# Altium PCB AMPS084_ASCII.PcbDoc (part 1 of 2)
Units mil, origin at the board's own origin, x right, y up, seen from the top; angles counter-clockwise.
Board outline 7000 x 5000 mil, 4 copper layers (Top Layer, Int 2 V-, Int 3 V+, Bottom Layer), stack 61.634 mil thick; 175 components, 69 nets, 389 pads, 136 vias.
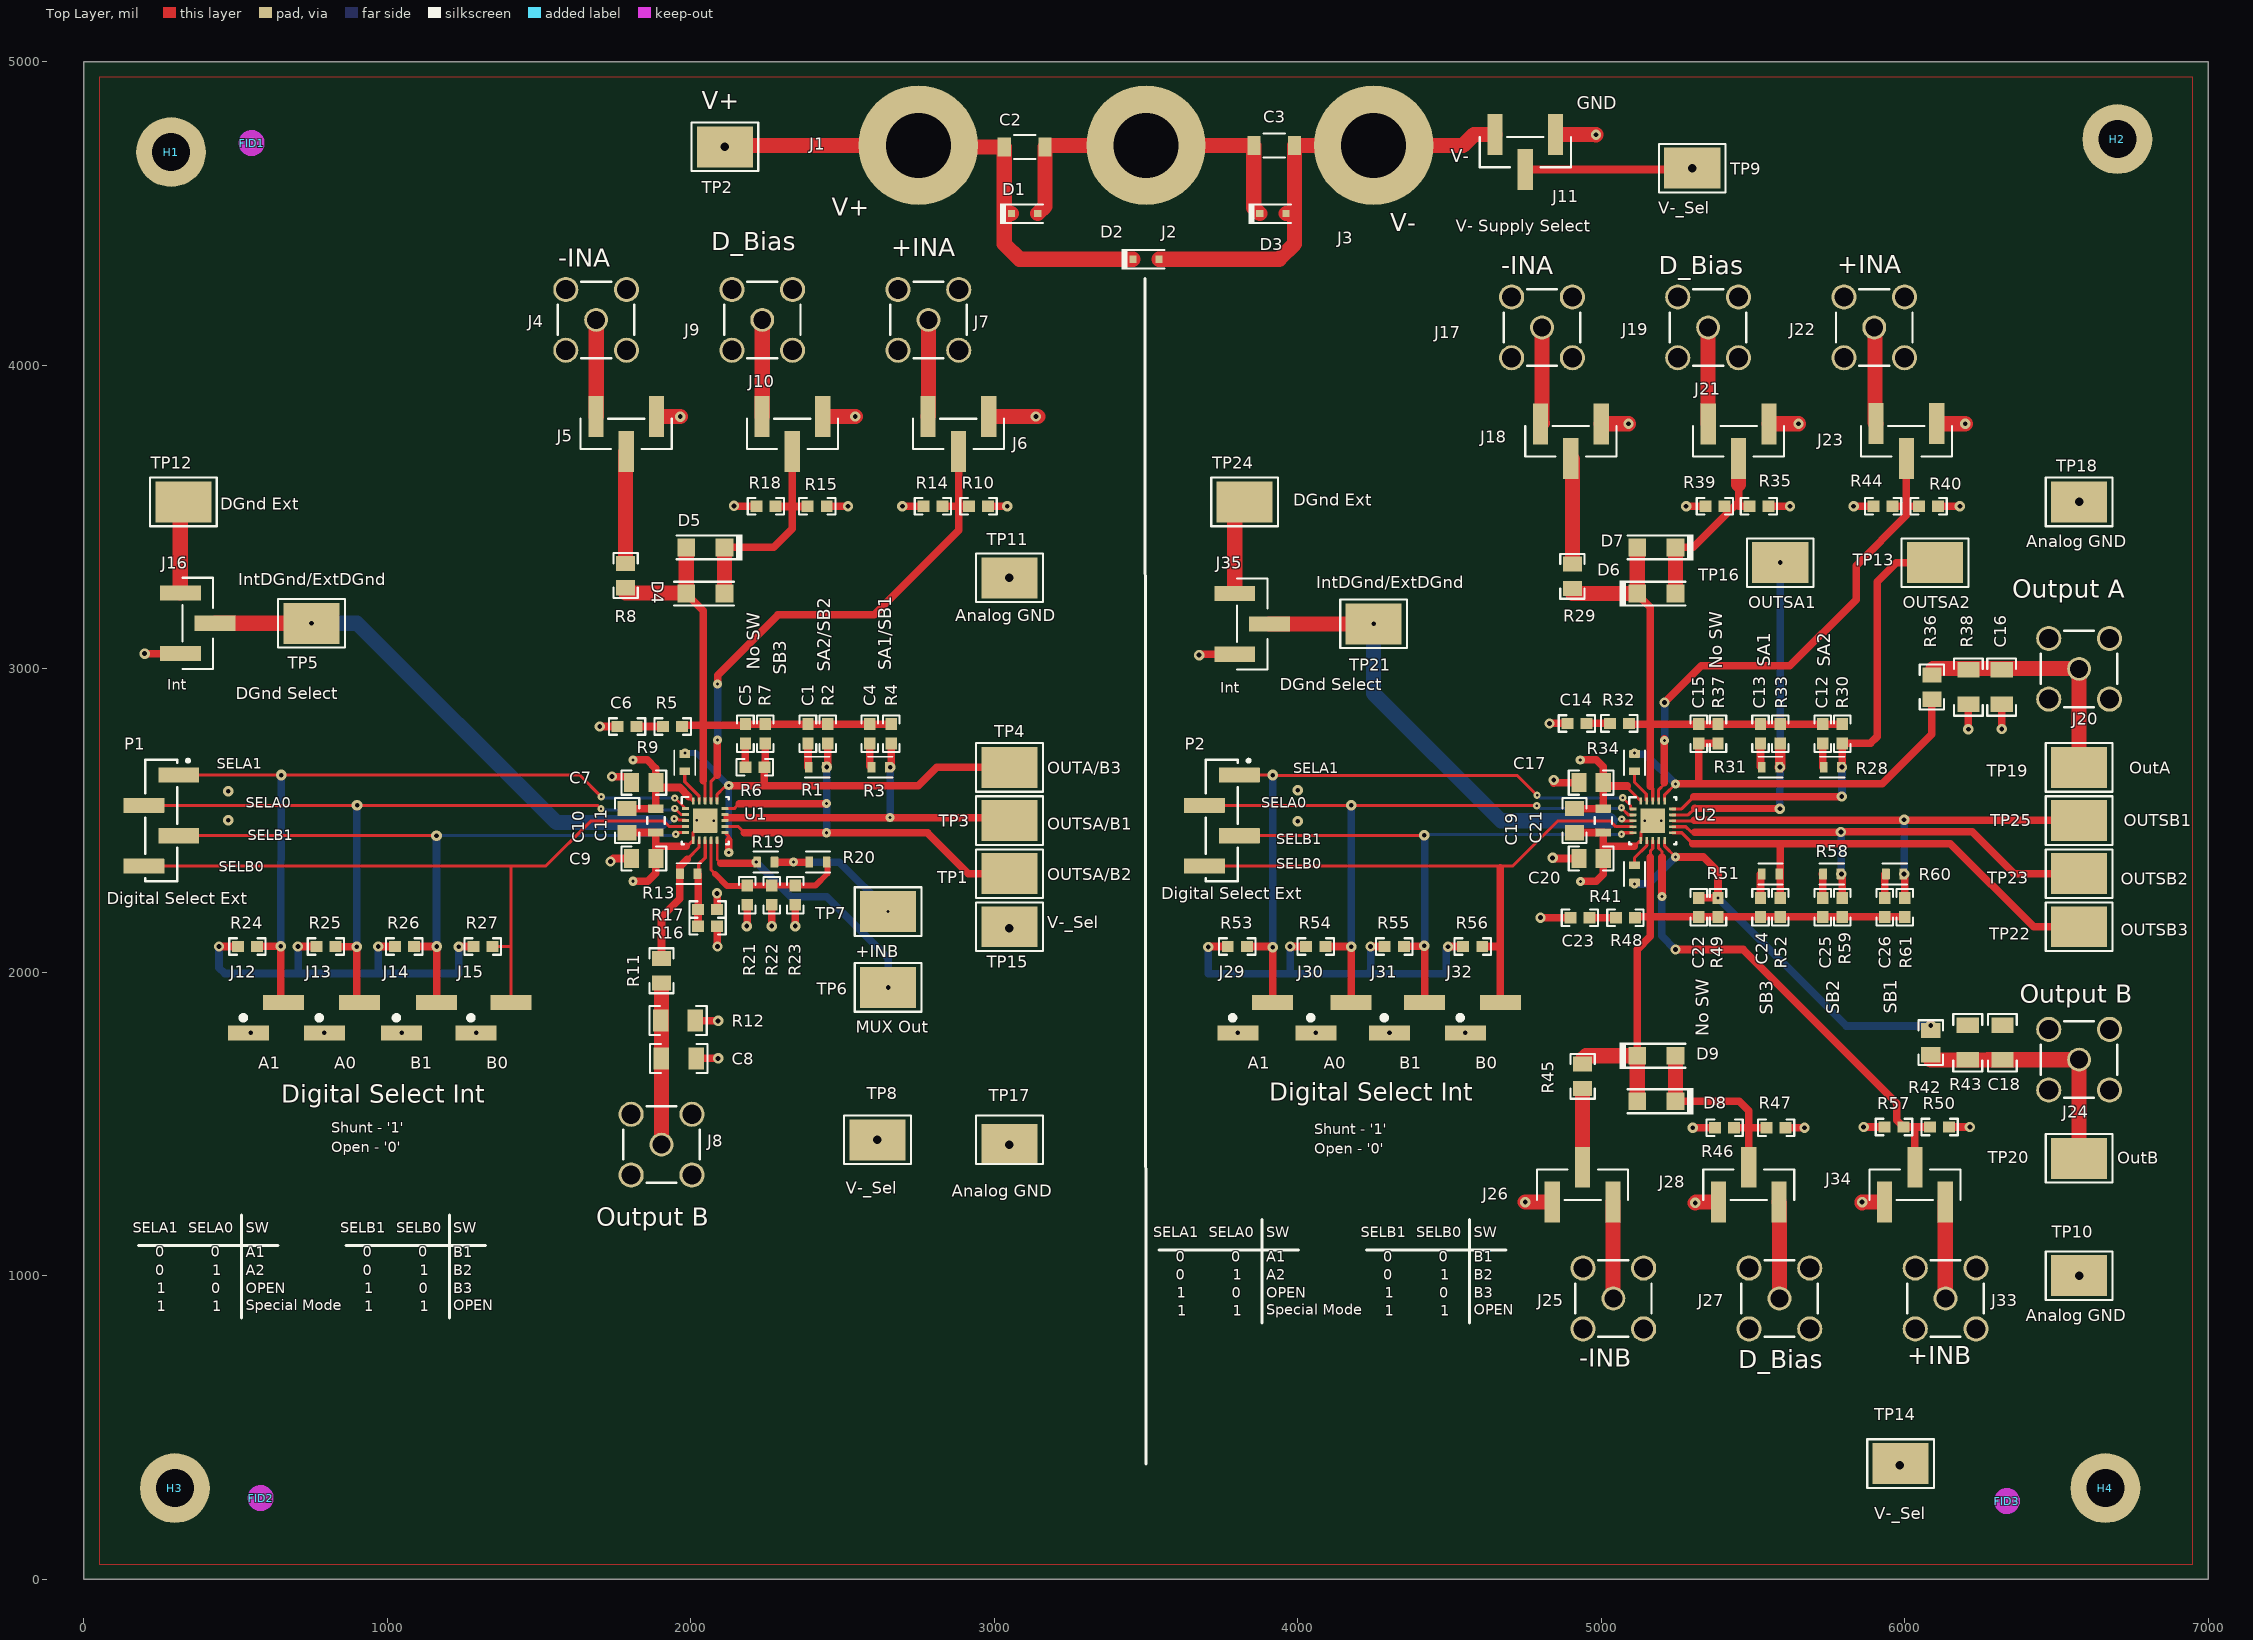
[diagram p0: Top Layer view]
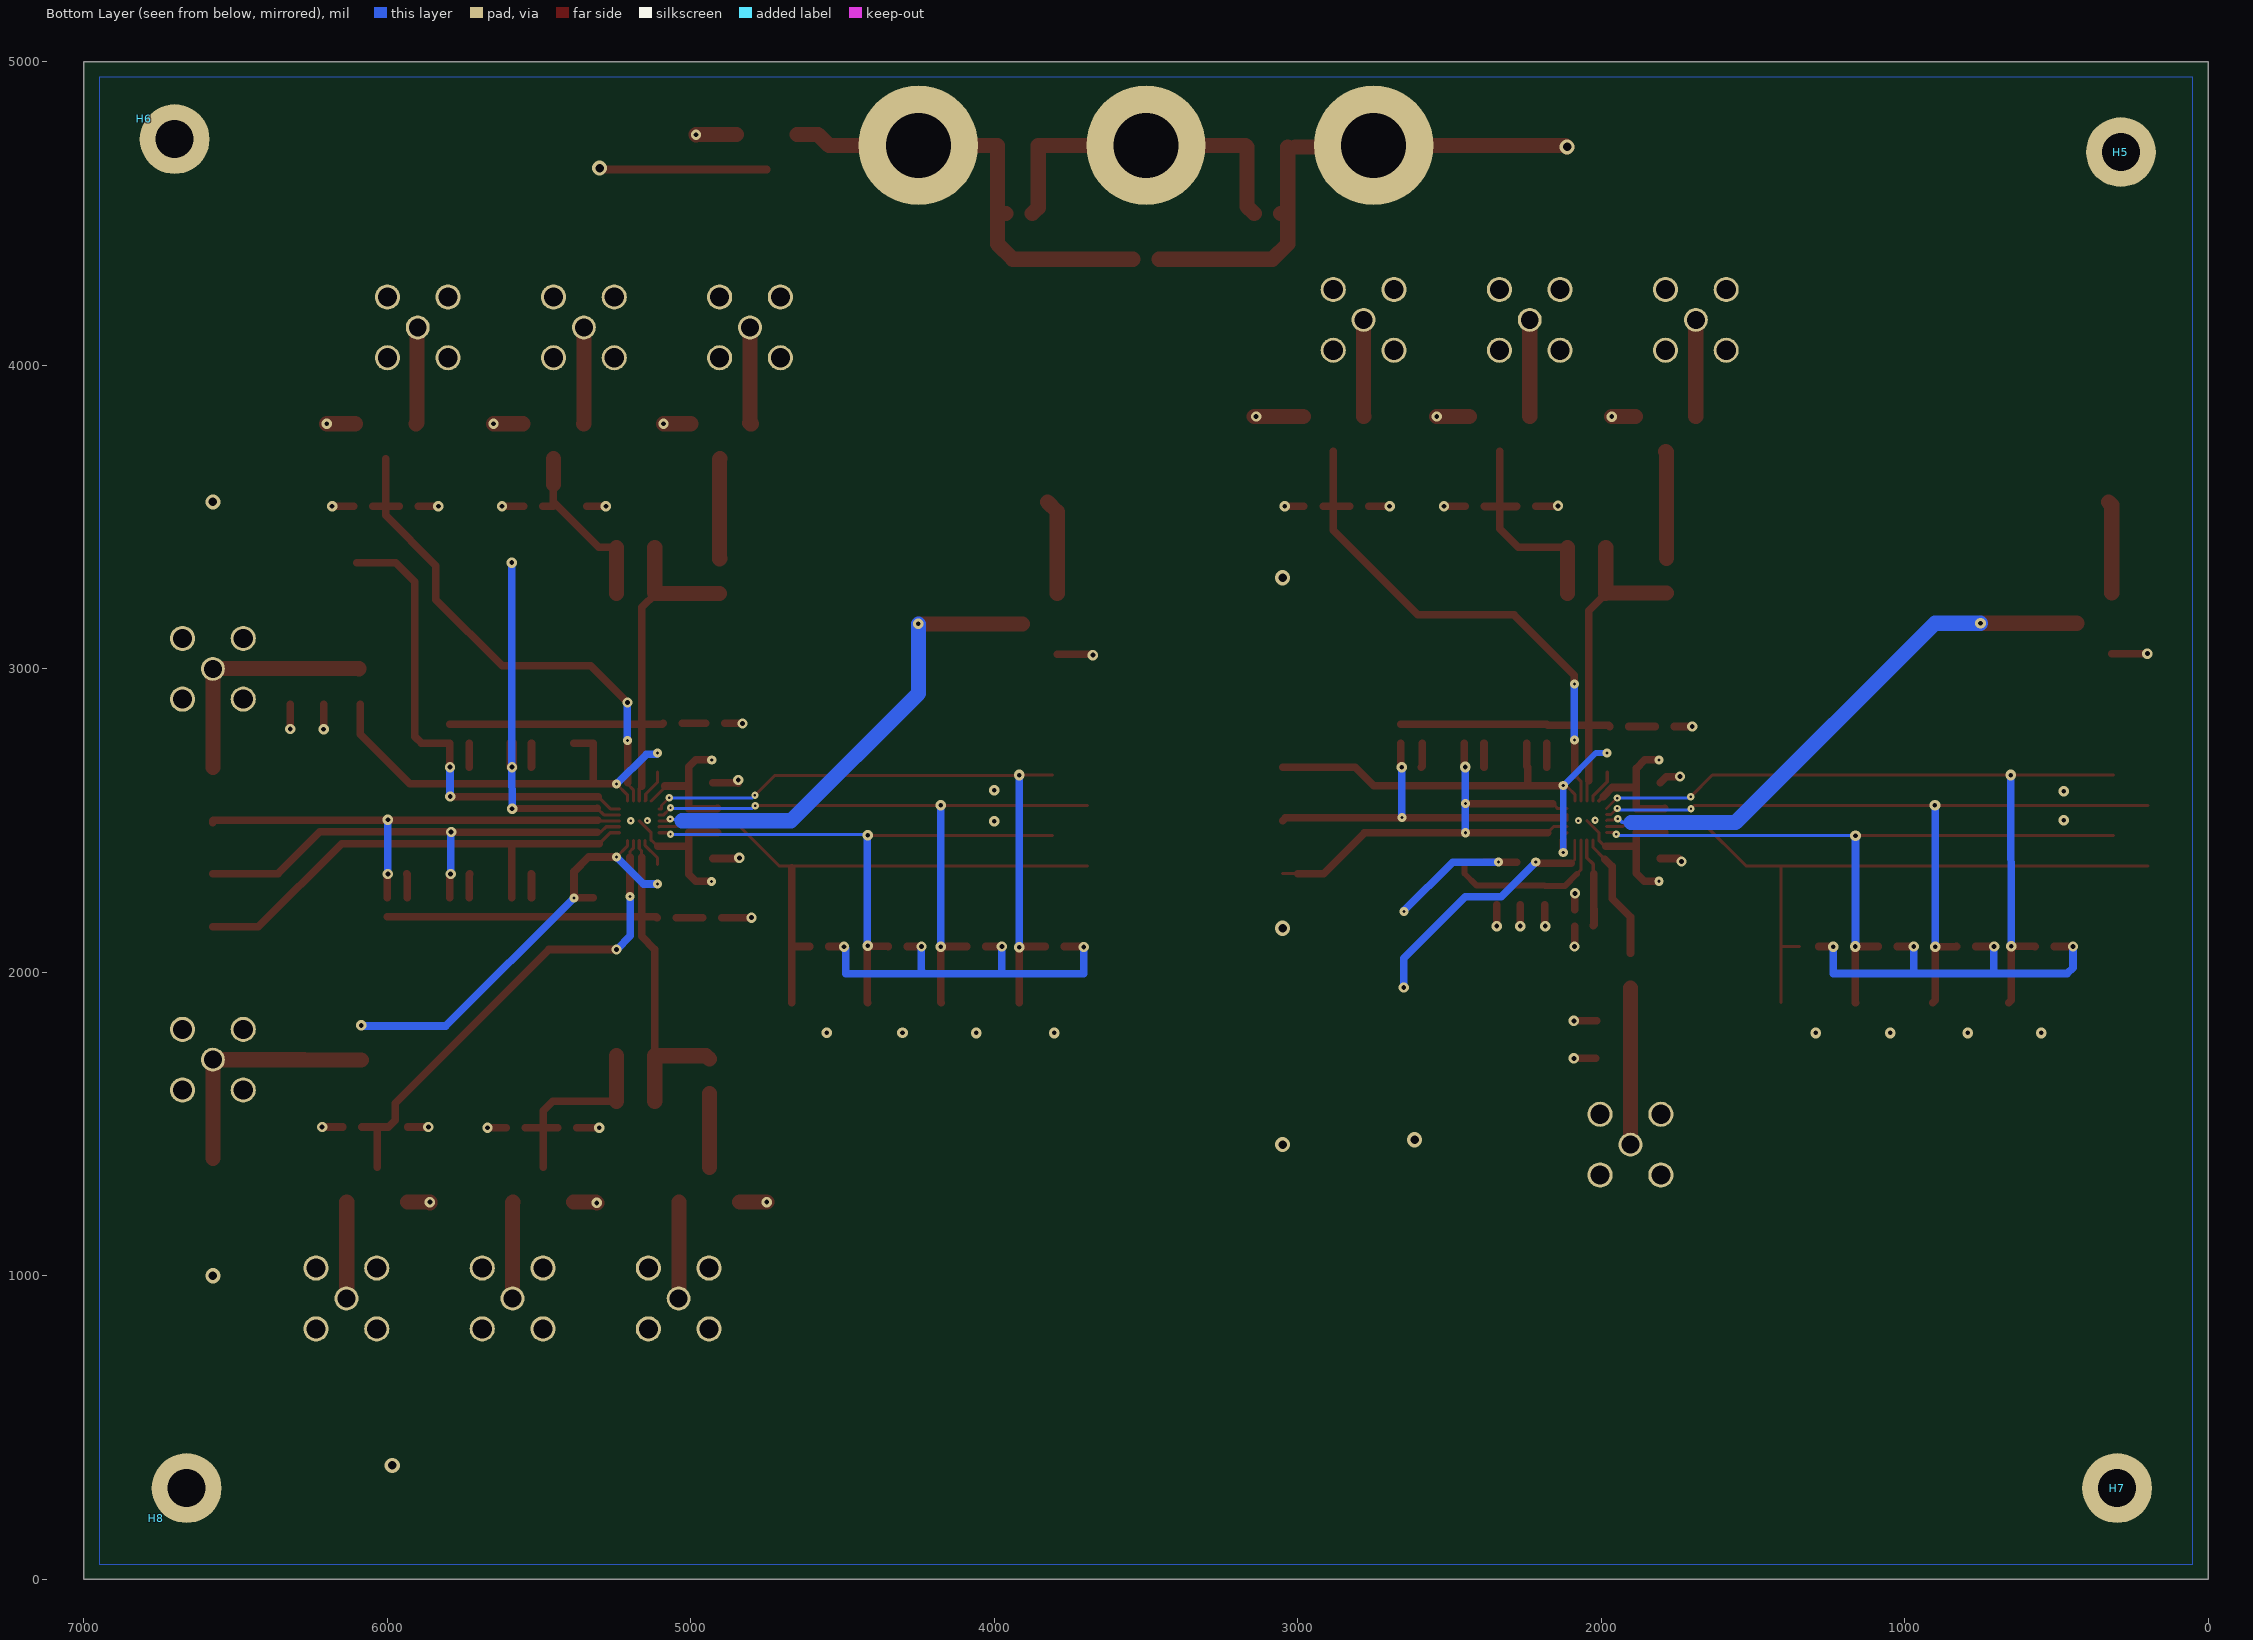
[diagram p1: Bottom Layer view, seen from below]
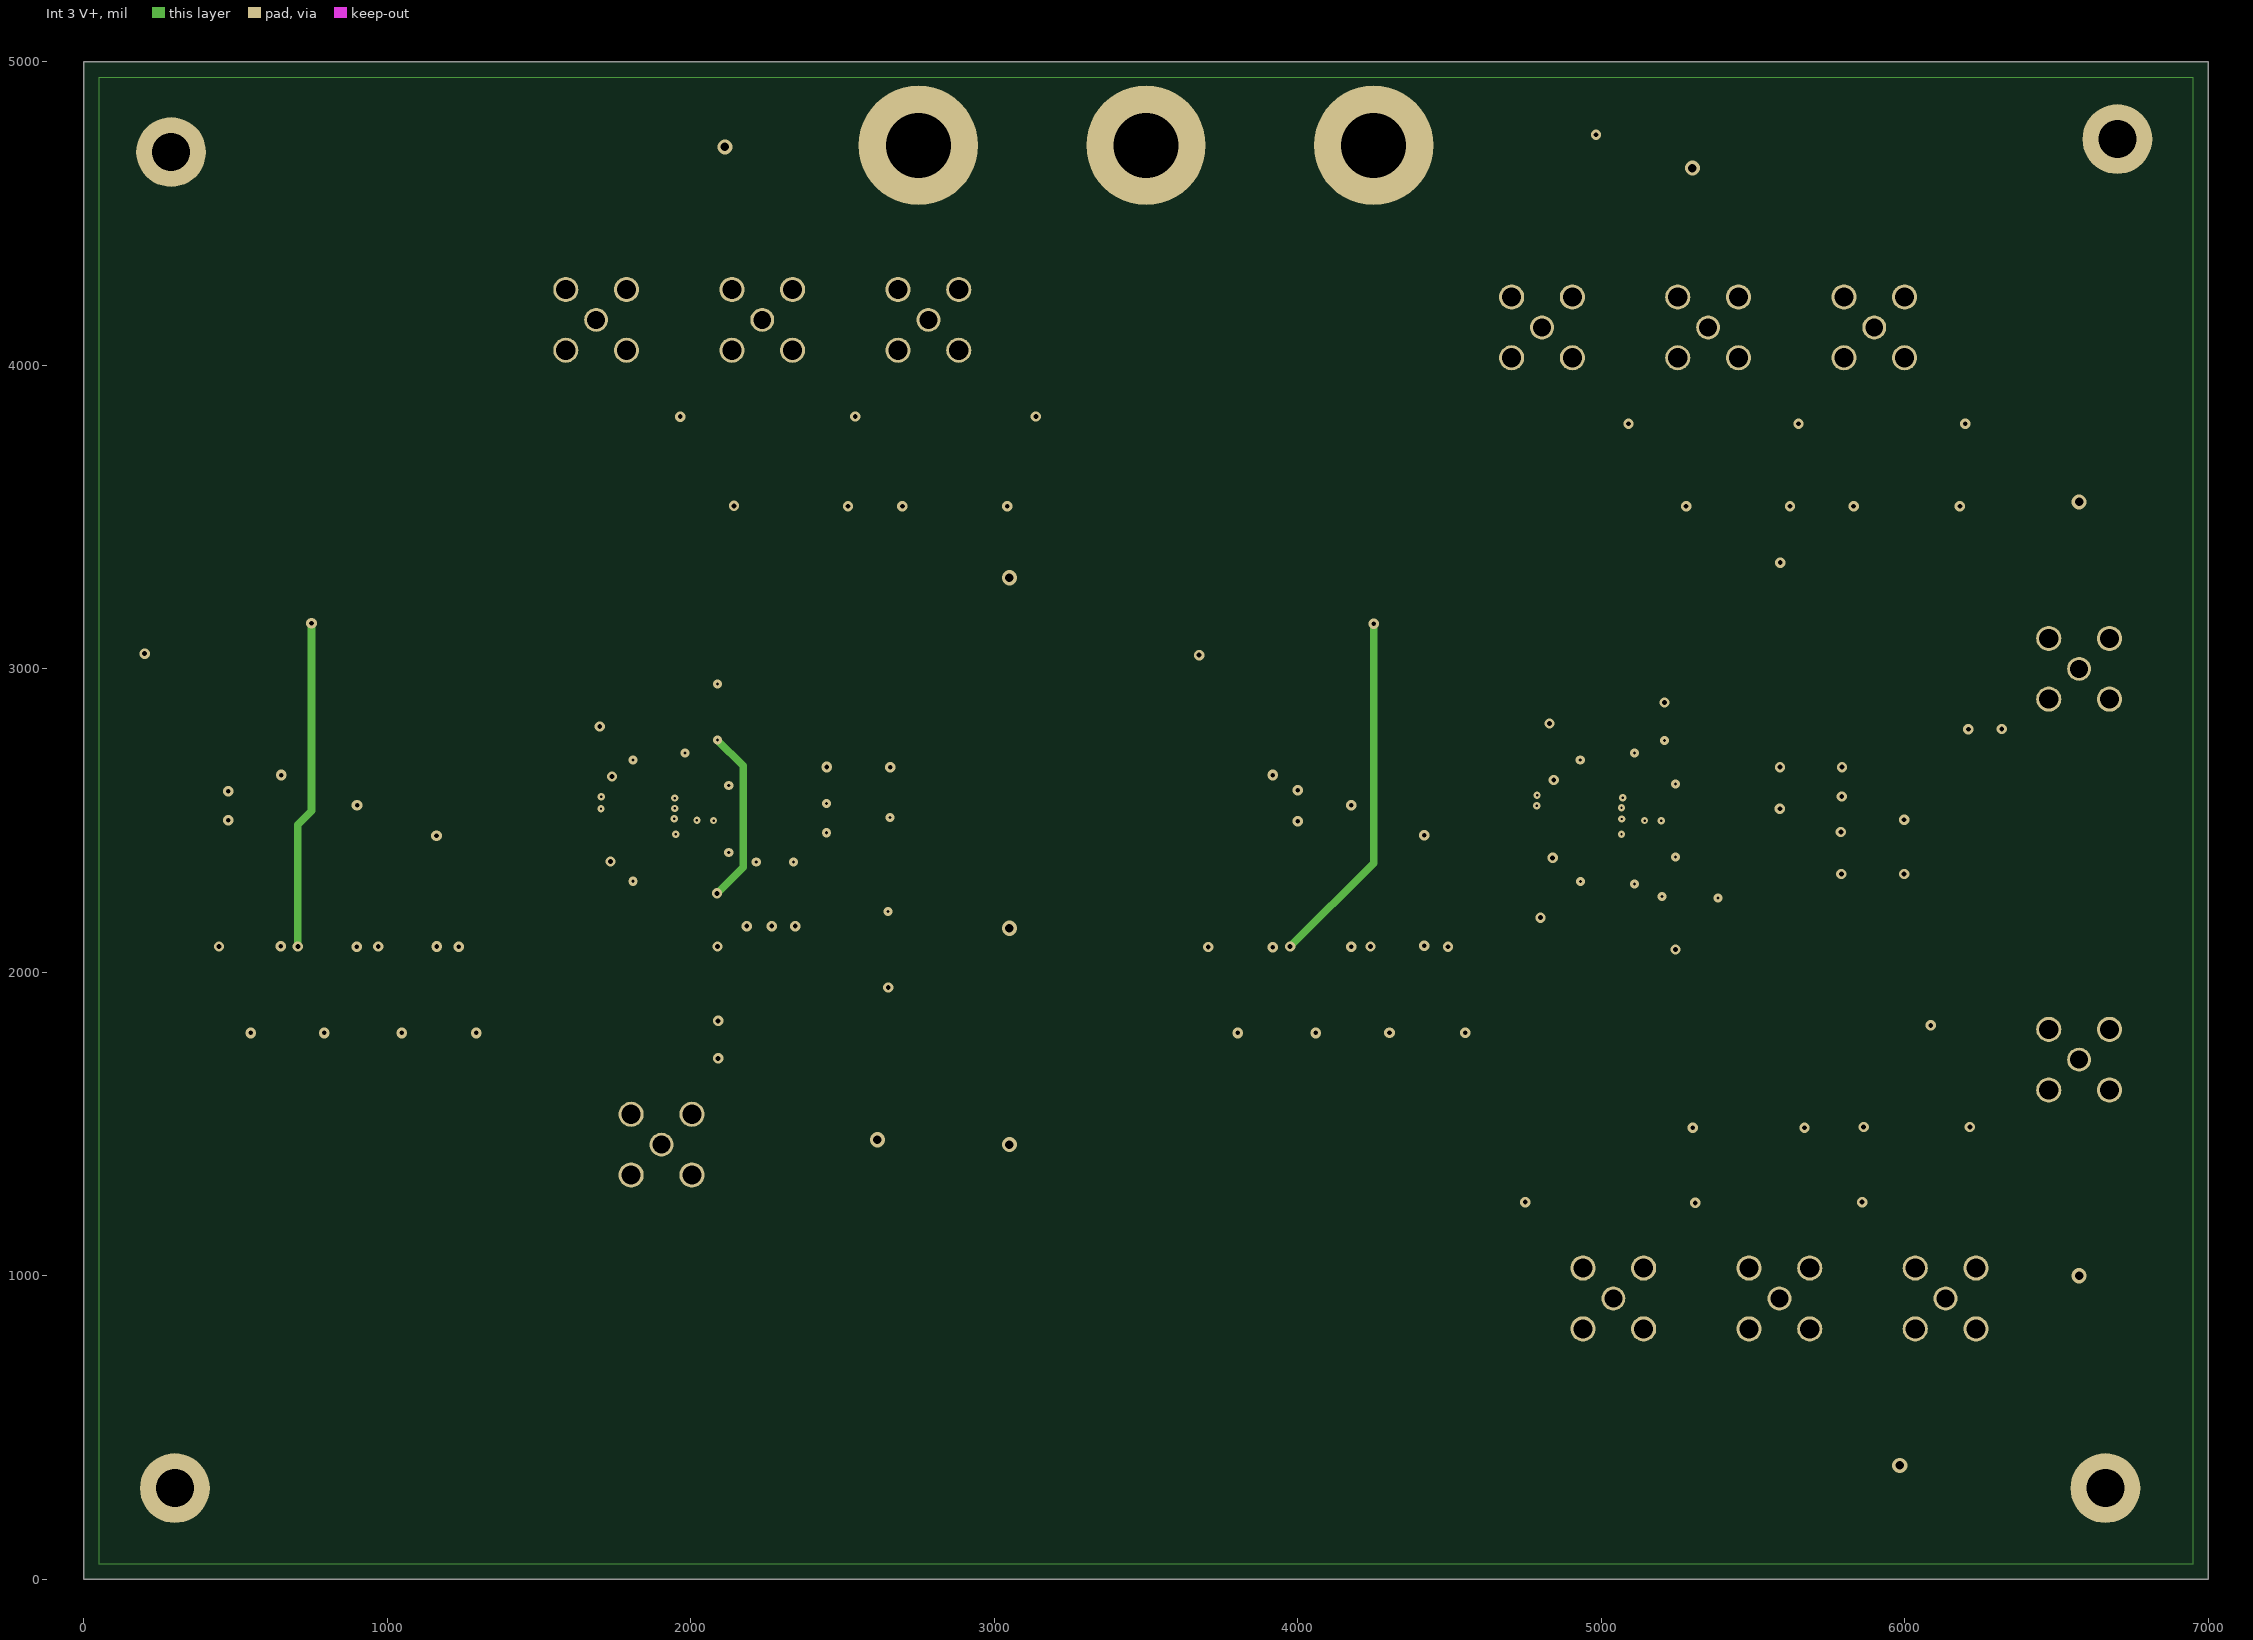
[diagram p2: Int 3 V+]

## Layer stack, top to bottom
Top Solder: solder mask 0.4, Solder Resist, Dk 3.5
Top Layer: signal copper 1.4
Dielectric 2: dielectric 10, Dk 4.2
Int 2 V-: signal copper 1.417
Dielectric1: core 36, FR-4, Dk 4.8
Int 3 V+: signal copper 1.417
Dielectric 3: dielectric 10, Dk 4.2
Bottom Layer: signal copper 1.4
Bottom Solder: solder mask 0.4, Solder Resist, Dk 3.5

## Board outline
0,0 7000,0 7000,5000 0,5000

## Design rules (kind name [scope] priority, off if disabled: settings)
AcuteAngle [All] p0: scope1count=1 scope1_0_kind=Board scope1_0_value=Board scope2count=1 scope2_0_kind=Board scope2_0_value=Board commentlength=0 minimum=4.50000000000000E+0001
AcuteAngle [All] p1: minimum=4.50000000000000E+0001 checktracksonly=FALSE
AssemblyTestPointUsage [All] p0: scope1count=1 scope1_0_kind=Board scope1_0_value=Board scope2count=1 scope2_0_kind=Board scope2_0_value=Board commentlength=0
AssemblyTestPointUsage [All] p1: valid=2
AssemblyTestpoint [All] p0: scope1count=1 scope1_0_kind=Board scope1_0_value=Board scope2count=1 scope2_0_kind=Board scope2_0_value=Board commentlength=0
BoardOutlineClearance [All] p0 off: scope1count=1 scope1_0_kind=Board scope1_0_value=Board scope2count=1 scope2_0_kind=Board scope2_0_value=Board commentlength=172 gap=75 // Protel DXP Scope 1 Expression Was: OnCopper and Not InComponentClass('Logo') and not InComponentClass('FiducialMark') and not InRegion(1000,500,4000,800) and not InPoly
BoardOutlineClearance BoardOutlineClearance_Poly [All] p0 off: scope1count=1 scope1_0_kind=Board scope1_0_value=Board scope2count=1 scope2_0_kind=Board scope2_0_value=Board commentlength=58 gap=25 // Protel DXP Scope 1 Expression Was: OnCopper and IsPoly
BoardOutlineClearance BoardOutlineClearance_MountingHoles [All] p0 off: scope1count=1 scope1_0_kind=Board scope1_0_value=Board scope2count=1 scope2_0_kind=Board scope2_0_value=Board commentlength=86 gap=39.37 // Protel DXP Scope 1 Expression Was: OnCopper and InComponentClass('Mounting Holes')
BoardOutlineClearance BoardOutlineClearance_MountingHoles [OnCopper and InComponentClass('Mounting Holes')] p1: gap=39.37 ignorepadtopadclearanceinfootprint=FALSE
BoardOutlineClearance BoardOutlineClearance_Poly [OnCopper and IsPoly] p2: gap=25 ignorepadtopadclearanceinfootprint=FALSE
BoardOutlineClearance [OnCopper and Not InComponentClass('Logo') and not InComponentClass('FiducialMark') and not InRegion(1000,500,4000,800) and not InPoly] p3: gap=75 ignorepadtopadclearanceinfootprint=FALSE
Clearance [All] p0: scope1count=1 scope1_0_kind=Board scope1_0_value=Board scope2count=1 scope2_0_kind=Board scope2_0_value=Board commentlength=0 gap=7.87
Clearance Clearance_FiducialMark [All] p0 off: scope1count=1 scope1_0_kind=Board scope1_0_value=Board scope2count=1 scope2_0_kind=Board scope2_0_value=Board commentlength=81 gap=0 // Protel DXP Scope 2 Expression Was: IsPad and InComponentClass('FiducialMark')
Clearance Clearance_Poly [All] p0 off: scope1count=1 scope1_0_kind=Board scope1_0_value=Board scope2count=1 scope2_0_kind=Board scope2_0_value=Board commentlength=48 gap=25 // Protel DXP Scope 1 Expression Was: InPolygon
Clearance Clearance_Keepouts [All] p0 off: scope1count=1 scope1_0_kind=Board scope1_0_value=Board scope2count=1 scope2_0_kind=Board scope2_0_value=Board commentlength=99 gap=0 // Protel DXP Scope 2 Expression Was: ((IsTrack Or IsArc) And Not InPoly) And IsFree and IsKeepOut
Clearance Clearance_Keepouts [((IsTrack Or IsArc) And Not InPoly) And IsFree and IsKeepOut vs ((IsTrack Or IsArc) And Not InPoly) And IsFree and IsKeepOut] p1: gap=0 ignorepadtopadclearanceinfootprint=FALSE
Clearance Clearance_Poly [InPolygon] p2: gap=25 ignorepadtopadclearanceinfootprint=TRUE
Clearance Clearance_FiducialMark [IsKeepOut and InComponentClass('FiducialMark') vs IsPad and InComponentClass('FiducialMark')] p3: gap=0 ignorepadtopadclearanceinfootprint=FALSE
Clearance [All] p4: gap=7.87 ignorepadtopadclearanceinfootprint=TRUE
ComponentClearance [All] p0: scope1count=1 scope1_0_kind=Board scope1_0_value=Board scope2count=1 scope2_0_kind=Board scope2_0_value=Board commentlength=0 gap=30 collisioncheckmode=3
ComponentClearance ComponentClearance_THtoTH [All] p0 off: scope1count=1 scope1_0_kind=Board scope1_0_value=Board scope2count=1 scope2_0_kind=Board scope2_0_value=Board commentlength=54 gap=30 collisioncheckmode=3 // Protel DXP Scope 2 Expression Was: IsThruComponent
ComponentClearance ComponentClearance_THtoSMT [All] p0 off: scope1count=1 scope1_0_kind=Board scope1_0_value=Board scope2count=1 scope2_0_kind=Board scope2_0_value=Board commentlength=53 gap=40 collisioncheckmode=3 // Protel DXP Scope 2 Expression Was: IsSMTComponent
ComponentClearance ComponentClearance_SmallPassives [All] p0 off: scope1count=1 scope1_0_kind=Board scope1_0_value=Board scope2count=1 scope2_0_kind=Board scope2_0_value=Board commentlength=508 gap=14.96 collisioncheckmode=3 // Protel DXP Scope 2 Expression Was: HasFootprint('0201*') or HasFootprint('0402*') or HasFootprint('0508') or HasFootprint('0603*') or HasFootprint('0612') or HasFootprint('0805*') or HasFootprint('0815*') or HasFootprint('0830*') or HasFootprint('1206*') or HasFootprint('1210*') or HasFootprint('1808*') or HasFootprint('1812*') or HasFootprint('1825*') or HasFootprint('2010*') or HasFootprint('2220*') or HasFootprint('2225*') or HasFootprint('2512*') or HasFootprint('2728*') or HasFootprint('3518*')
ComponentClearance ComponentClearance_MountingHoles [All] p0: scope1count=1 scope1_0_kind=ComponentClass scope1_0_value="Mounting Holes" scope2count=1 scope2_0_kind=Board scope2_0_value=Board commentlength=0 gap=250 collisioncheckmode=3
ComponentClearance ComponentClearance_ScrewToNut [All] p0 off: scope1count=1 scope1_0_kind=Board scope1_0_value=Board scope2count=1 scope2_0_kind=Board scope2_0_value=Board commentlength=71 gap=5 collisioncheckmode=3 // Protel DXP Scope 2 Expression Was: (HasFootprint('Keystone_1902C'))
ComponentClearance ComponentClearance_Logo [All] p0: scope1count=1 scope1_0_kind=ComponentClass scope1_0_value=Logo scope2count=1 scope2_0_kind=Board scope2_0_value=Board commentlength=0 gap=50 collisioncheckmode=3
ComponentClearance ComponentClearance_Shunt [All] p0: scope1count=1 scope1_0_kind=ComponentClass scope1_0_value=Header scope2count=1 scope2_0_kind=ComponentClass scope2_0_value=Shunt commentlength=0 gap=0 collisioncheckmode=3
ComponentClearance ComponentClearance_MountingHoles_FiducialMarks [All] p0: scope1count=1 scope1_0_kind=ComponentClass scope1_0_value="Mounting Holes" scope2count=1 scope2_0_kind=ComponentClass scope2_0_value=FiducialMark commentlength=0 gap=50 collisioncheckmode=3
ComponentClearance ComponentClearance_MountingHoles_FiducialMarks [InComponentClass('Mounting Holes') vs InComponentClass('FiducialMark')] p1: gap=50 collisioncheckmode=3 verticalgap=10 showdistances=FALSE
ComponentClearance ComponentClearance_Shunt [InComponentClass('Header') vs InComponentClass('Shunt')] p2: gap=0 collisioncheckmode=3 verticalgap=0 showdistances=FALSE
ComponentClearance ComponentClearance_Logo [InComponentClass('Logo')] p3: gap=50 collisioncheckmode=3 verticalgap=10 showdistances=FALSE
ComponentClearance ComponentClearance_ScrewToNut [(HasFootprint('NY PMS 440 0025 PH')) vs (HasFootprint('Keystone_1902C'))] p4: gap=5 collisioncheckmode=3 verticalgap=10 showdistances=FALSE
ComponentClearance ComponentClearance_MountingHoles [InComponentClass('Mounting Holes')] p5: gap=250 collisioncheckmode=3 verticalgap=100000 showdistances=FALSE
ComponentClearance ComponentClearance_SmallPassives [HasFootprint('0201*') or HasFootprint('0402*') or HasFootprint('0508') or HasFootprint('0603*') or HasFootprint('0612') or HasFootprint('0805*') or HasFootprint('0815*') or HasFootprint('0830*') or HasFootprint('1206*') or HasFootprint('1210*') or HasFootprint('1808*') or HasFootprint('1812*') or HasFootprint('1825*') or HasFootprint('2010*') or HasFootprint('2220*') or HasFootprint('2225*') or HasFootprint('2512*') or HasFootprint('2728*') or HasFootprint('3518*') vs HasFootprint('0201*') or HasFootprint('0402*') or HasFootprint('0508') or HasFootprint('0603*') or HasFootprint('0612') or HasFootprint('0805*') or HasFootprint('0815*') or HasFootprint('0830*') or HasFootprint('1206*') or HasFootprint('1210*') or HasFootprint('1808*') or HasFootprint('1812*') or HasFootprint('1825*') or HasFootprint('2010*') or HasFootprint('2220*') or HasFootprint('2225*') or HasFootprint('2512*') or HasFootprint('2728*') or HasFootprint('3518*')] p6: gap=14.96 collisioncheckmode=3 verticalgap=10 showdistances=FALSE
ComponentClearance ComponentClearance_THtoSMT [IsThruComponent vs IsSMTComponent] p7: gap=40 collisioncheckmode=3 verticalgap=30 showdistances=FALSE
ComponentClearance ComponentClearance_THtoTH [IsThruComponent vs IsThruComponent] p8: gap=30 collisioncheckmode=3 verticalgap=30 showdistances=FALSE
ComponentClearance [All] p9: gap=30 collisioncheckmode=3 verticalgap=10 showdistances=FALSE
DiffPairsRouting [All] p0: scope1count=1 scope1_0_kind=Board scope1_0_value=Board scope2count=1 scope2_0_kind=Board scope2_0_value=Board commentlength=0
DiffPairsRouting [All] p1: maxlimit=100 minlimit=10 mostfreqgap=10 toplayer_minwidth=15 toplayer_maxwidth=15 toplayer_prefwidth=15 midlayer1_minwidth=15 midlayer1_maxwidth=15 midlayer1_prefwidth=15 midlayer2_minwidth=15 midlayer2_maxwidth=15 midlayer2_prefwidth=15 bottomlayer_minwidth=15 bottomlayer_maxwidth=15 bottomlayer_prefwidth=15 maxuncoupledlength=1000
FabricationTestPointUsage TestPointUsage [All] p0: scope1count=1 scope1_0_kind=Board scope1_0_value=Board scope2count=1 scope2_0_kind=Board scope2_0_value=Board commentlength=0 valid=2 allowmultiple=FALSE
FabricationTestPointUsage TestPointUsage [All] p1: valid=2 allowmultiple=FALSE
FabricationTestpoint Testpoint [All] p0: scope1count=1 scope1_0_kind=Board scope1_0_value=Board scope2count=1 scope2_0_kind=Board scope2_0_value=Board commentlength=0 side=3 testpointundercomponent=TRUE minsize=40 maxsize=100 preferedsize=60 minholesize=0 maxholesize=40 preferedholesize=32 testpointgrid=1
FabricationTestpoint Testpoint [All] p1: side=3 testpointundercomponent=TRUE minsize=40 maxsize=100 preferedsize=60 minholesize=0 maxholesize=40 preferedholesize=32 testpointgrid=1 allowsidetop=TRUE allowsidebottom=TRUE usegrid=TRUE gridtolerance=0.01
FanoutControl Fanout_Small [All] p0 off: scope1count=1 scope1_0_kind=Board scope1_0_value=Board scope2count=1 scope2_0_kind=Board scope2_0_value=Board commentlength=84 // Protel DXP Scope 1 Expression Was: (CompPinCount < 5)   Fanout_Small (Default Rule)
FanoutControl Fanout_Default [All] p0: scope1count=1 scope1_0_kind=Board scope1_0_value=Board scope2count=1 scope2_0_kind=Board scope2_0_value=Board commentlength=30 // Fanout_Default (Default Rule)
FanoutControl Fanout_SOIC [All] p0 off: scope1count=1 scope1_0_kind=Board scope1_0_value=Board scope2count=1 scope2_0_kind=Board scope2_0_value=Board commentlength=71 // Protel DXP Scope 1 Expression Was: IsSOIC   Fanout_SOIC (Default Rule)
FanoutControl Fanout_BGA [All] p0 off: scope1count=1 scope1_0_kind=Board scope1_0_value=Board scope2count=1 scope2_0_kind=Board scope2_0_value=Board commentlength=69 // Protel DXP Scope 1 Expression Was: IsBGA   Fanout_BGA (Default Rule)
FanoutControl Fanout_LCC [All] p0 off: scope1count=1 scope1_0_kind=Board scope1_0_value=Board scope2count=1 scope2_0_kind=Board scope2_0_value=Board commentlength=69 // Protel DXP Scope 1 Expression Was: IsLCC   Fanout_LCC (Default Rule)
FanoutControl Fanout_LCC [IsLCC] p1: bgadir=Out bgaviamode=Centered fanoutstyle=Auto fanoutdirection=Alternating viagrid=1 // Fanout_LCC (Default Rule)
FanoutControl Fanout_BGA [IsBGA] p2: bgadir=Out bgaviamode=Centered fanoutstyle=Auto fanoutdirection=Alternating viagrid=1 // Fanout_BGA (Default Rule)
FanoutControl Fanout_Default [All] p4: bgadir=Out bgaviamode=Centered fanoutstyle=Auto fanoutdirection=Alternating viagrid=1 // Fanout_Default (Default Rule)
FanoutControl Fanout_Small [(CompPinCount < 5)] p5: bgadir=Out bgaviamode=Centered fanoutstyle=Auto fanoutdirection=OutThenIn viagrid=1 // Fanout_Small (Default Rule)
Height [All] p0: scope1count=1 scope1_0_kind=Board scope1_0_value=Board scope2count=1 scope2_0_kind=Board scope2_0_value=Board commentlength=0
HoleSize [All] p0: scope1count=1 scope1_0_kind=Board scope1_0_value=Board scope2count=1 scope2_0_kind=Board scope2_0_value=Board commentlength=0 absolutevalues=TRUE maxlimit=251 minlimit=7.87 maxpercent=80.000 minpercent=20.000
HoleSize [All] p1: absolutevalues=TRUE maxlimit=251 minlimit=7.87 maxpercent=80.000 minpercent=20.000
HoleToHoleClearance [All] p0: scope1count=1 scope1_0_kind=Board scope1_0_value=Board scope2count=1 scope2_0_kind=Board scope2_0_value=Board commentlength=0
LayerPairs [All] p0: scope1count=1 scope1_0_kind=Board scope1_0_value=Board scope2count=1 scope2_0_kind=Board scope2_0_value=Board commentlength=0 enforce=TRUE
MinimumAnnularRing [All] p0: scope1count=1 scope1_0_kind=Board scope1_0_value=Board scope2count=1 scope2_0_kind=Board scope2_0_value=Board commentlength=0 minimumring=7.87
MinimumAnnularRing MinimumAnnularRing_ThermalPadVias [All] p0 off: scope1count=1 scope1_0_kind=Board scope1_0_value=Board scope2count=1 scope2_0_kind=Board scope2_0_value=Board commentlength=63 minimumring=5.91 // Protel DXP Scope 1 Expression Was: IsVia and InAnyComponent
MinimumAnnularRing MinimumAnnularRing_ThermalPadVias [IsVia and InAnyComponent] p1: minimumring=5.91
MinimumAnnularRing [All] p2: minimumring=7.87
MinimumSolderMaskSliver [All] p0: scope1count=1 scope1_0_kind=Board scope1_0_value=Board scope2count=1 scope2_0_kind=Board scope2_0_value=Board commentlength=0
MinimumSolderMaskSliver MinimumSolderMaskSliver_Logo [All] p0: scope1count=1 scope1_0_kind=ComponentClass scope1_0_value=Logo scope2count=1 scope2_0_kind=ComponentClass scope2_0_value=Logo commentlength=0
MinimumSolderMaskSliver MinimumSolderMaskSliver_Logo [InComponentClass('Logo') vs InComponentClass('Logo')] p1: minsoldermaskwidth=0.7
MinimumSolderMaskSliver [All] p2: minsoldermaskwidth=3.94
NetAntennae [All] p0: scope1count=1 scope1_0_kind=Board scope1_0_value=Board scope2count=1 scope2_0_kind=Board scope2_0_value=Board commentlength=0
PasteMaskExpansion [All] p0: scope1count=1 scope1_0_kind=Board scope1_0_value=Board scope2count=1 scope2_0_kind=Board scope2_0_value=Board commentlength=0 expansion=0
PlaneClearance [All] p0: scope1count=1 scope1_0_kind=Board scope1_0_value=Board scope2count=1 scope2_0_kind=Board scope2_0_value=Board commentlength=0 clearance=20
PlaneConnect [All] p0: scope1count=1 scope1_0_kind=Board scope1_0_value=Board scope2count=1 scope2_0_kind=Board scope2_0_value=Board commentlength=0 planeconnectstyle=Relief reliefexpansion=10 reliefentries=4 reliefconductorwidth=10 reliefairgap=10
PlaneConnect [All] p1: planeconnectstyle=Relief reliefexpansion=10 reliefentries=4 reliefconductorwidth=10 reliefairgap=10
PolygonConnect [All] p0: scope1count=1 scope1_0_kind=Board scope1_0_value=Board scope2count=1 scope2_0_kind=Board scope2_0_value=Board commentlength=0 connectstyle=Relief reliefconductorwidth=10 reliefentries=4 polygonreliefangle="90 Angle"
PolygonConnect [All] p1: connectstyle=Relief reliefconductorwidth=10 reliefentries=4 polygonreliefangle="90 Angle" airgapwidth=10
RoutingCorners [All] p0: scope1count=1 scope1_0_kind=Board scope1_0_value=Board scope2count=1 scope2_0_kind=Board scope2_0_value=Board commentlength=0 cornerstyle=45-Degree minsetback=100 maxsetback=100
RoutingLayers [All] p0: scope1count=1 scope1_0_kind=Board scope1_0_value=Board scope2count=1 scope2_0_kind=Board scope2_0_value=Board commentlength=0 top layer=Automatic mid layer 1=Automatic mid layer 2=Automatic bottom layer=Automatic
RoutingPriority [All] p0: scope1count=1 scope1_0_kind=Board scope1_0_value=Board scope2count=1 scope2_0_kind=Board scope2_0_value=Board commentlength=0
RoutingTopology [All] p0: scope1count=1 scope1_0_kind=Board scope1_0_value=Board scope2count=1 scope2_0_kind=Board scope2_0_value=Board commentlength=0 topology=Shortest
RoutingVias [All] p0: scope1count=1 scope1_0_kind=Board scope1_0_value=Board scope2count=1 scope2_0_kind=Board scope2_0_value=Board commentlength=0 holewidth=16 width=34 viastyle="Through Hole" minholewidth=7.87 minwidth=18 maxholewidth=40 maxwidth=65
RoutingVias ThermalPadVias [All] p0 off: scope1count=1 scope1_0_kind=Board scope1_0_value=Board scope2count=1 scope2_0_kind=Board scope2_0_value=Board commentlength=63 holewidth=7.87 width=19.68 viastyle="Through Hole" minholewidth=7.87 minwidth=18 maxholewidth=12.99 maxwidth=23.62 // Protel DXP Scope 1 Expression Was: IsVia and InAnyComponent
RoutingVias ThermalPadVias [IsVia and InAnyComponent] p1: holewidth=7.87 width=19.68 viastyle="Through Hole" minholewidth=7.87 minwidth=18 maxholewidth=12.99 maxwidth=23.62
RoutingVias [All] p2: holewidth=16 width=34 viastyle="Through Hole" minholewidth=7.87 minwidth=18 maxholewidth=40 maxwidth=65
ShortCircuit [All] p0: scope1count=1 scope1_0_kind=Board scope1_0_value=Board scope2count=1 scope2_0_kind=Board scope2_0_value=Board commentlength=0 allowed=FALSE
SilkToBoardRegionClearance [All] p0 off: scope1count=1 scope1_0_kind=Board scope1_0_value=Board scope2count=1 scope2_0_kind=Board scope2_0_value=Board commentlength=130 // Protel DXP Scope 1 Expression Was: Not ((IsComment or IsDesignator) And (Hide <> 'False')) and not InRegion(1000,500,4000,800)
SilkToBoardRegionClearance [Not ((IsComment or IsDesignator) And (Hide <> 'False')) and not InRegion(1000,500,4000,800)] p1:
SilkToSilkClearance [All] p0: scope1count=1 scope1_0_kind=Board scope1_0_value=Board scope2count=1 scope2_0_kind=Board scope2_0_value=Board commentlength=0
SilkToSilkClearance SilkToSilkClearance_Pb-FreeLogo [All] p0 off: scope1count=1 scope1_0_kind=Board scope1_0_value=Board scope2count=1 scope2_0_kind=Board scope2_0_value=Board commentlength=120 // Protel DXP Scope 2 Expression Was: (HasFootprint('Pb-Free_Overlay_Medium') OR HasFootprint('Pb-Free_Overlay_Small'))
SilkToSilkClearance SilkToSilkClearance_Pb-FreeLogo [(HasFootprint('Pb-Free_Overlay_Medium') OR HasFootprint('Pb-Free_Overlay_Small')) vs (HasFootprint('Pb-Free_Overlay_Medium') OR HasFootprint('Pb-Free_Overlay_Small'))] p1: silktosilkclearance=0
SilkToSilkClearance [All] p2: silktosilkclearance=3.94
SilkToSolderMaskClearance "Silk to Solder Mask Opening" [All] p0: scope1count=1 scope1_0_kind=Board scope1_0_value=Board scope2count=1 scope2_0_kind=Board scope2_0_value=Board commentlength=0
SilkToSolderMaskClearance SilkToComponentPadClearance [All] p0 off: scope1count=1 scope1_0_kind=Board scope1_0_value=Board scope2count=1 scope2_0_kind=Board scope2_0_value=Board commentlength=87 // Protel DXP Scope 1 Expression Was: (IsPad or IsFill or IsRegion) and InAnycomponent
SilkToSolderMaskClearance SilkToComponentPadClearance [(IsPad or IsFill or IsRegion) and InAnycomponent] p1: minsilkscreentomaskgap=5 clearancetoexposedcopper=TRUE
SilkToSolderMaskClearance "Silk to Solder Mask Opening" [All] p2: minsilkscreentomaskgap=3.94 clearancetoexposedcopper=FALSE
SolderMaskExpansion [All] p0: scope1count=1 scope1_0_kind=Board scope1_0_value=Board scope2count=1 scope2_0_kind=Board scope2_0_value=Board commentlength=0 expansion=1.97
SolderMaskExpansion [All] p1: expansion=1.97
UnRoutedNet [All] p0: scope1count=1 scope1_0_kind=Board scope1_0_value=Board scope2count=1 scope2_0_kind=Board scope2_0_value=Board commentlength=0
UnRoutedNet [All] p1: checkbadconnections=TRUE
UnpouredPolygon [All] p0: scope1count=1 scope1_0_kind=Board scope1_0_value=Board scope2count=1 scope2_0_kind=Board scope2_0_value=Board commentlength=0
Width [All] p0: scope1count=1 scope1_0_kind=Board scope1_0_value=Board scope2count=1 scope2_0_kind=Board scope2_0_value=Board commentlength=0 maxlimit=100 minlimit=6 preferedwidth=10
Width [All] p1: maxlimit=100 minlimit=6 preferedwidth=10 checkconnectedcopper=TRUE
14 further rules are at their usual default settings.

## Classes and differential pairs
component class Shunt: SH-J?
component class AMPS084_schematic1: C1 C2 C3 C4 C5 C6 C7 C8 C9 C10 C11 D1 D2 D3 D4 D5 J1 J2 J3 J4 J5 J6 J7 J8 J9 J10 J11 J12 J13 J14 J15 J16 P1 R1 R2 R3 R4 R5 R6 R7 R8 R9 R10 R11 R12 R13 R14 R15 R16 R17 R18 R19 R20 R21 R22 R23 R24 R25 R26 R27 TP1 TP2 TP3 TP4 TP5 TP6 TP7 TP8 TP9 TP10 TP11 TP12 U1
component class Header: J5 J7 J10 J11 J12 J13 J14 J15 J16 J18 J21 J23 J26 J28 J29 J30 J31 J32 J34 J35
component class AMPS084_schematic2: C12 C13 C14 C15 C16 C17 C18 C19 C20 C21 C22 C23 C24 C25 C26 D6 D7 D8 D9 J17 J18 J19 J20 J21 J22 J23 J24 J25 J26 J27 J28 J29 J30 J31 J32 J33 J34 J35 P2 R28 R29 R30 R31 R32 R33 R34 R35 R36 R37 R38 R39 R40 R41 R42 R43 R44 R45 R46 R47 R48 R49 R50 R51 R52 R53 R54 R55 R56 R57 R58 R59 R60 R61 TP13 TP14 TP15 TP16 TP17 TP18 TP19 TP20 TP21 TP22 TP23 TP24 TP25 U2
component class AMPS084_Hardware: FID1 FID2 FID3 H1 H2 H3 H4 H5 H6 H7 H8 ZZ1 ZZ2 ZZ3 ZZ4
component class FiducialMark: FID1 FID2 FID3
component class AssemblyNote: ZZ1 ZZ2 ZZ3 ZZ4

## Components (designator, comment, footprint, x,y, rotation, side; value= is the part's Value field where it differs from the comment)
C1 "06035A220JAT2A" 0603 2386,2786 r90 top
C2 "C3216X7R1E106M160AE" 1206_190 3100,4720 r180 top
C3 "C3216X7R1E106M160AE" 1206_190 3922.26,4725 r180 top
C4 "06035A220JAT2A" 0603 2590,2786 r90 top
C5 "C0603C102J5GACTU" 0603 2180,2786 r90 top
C6 "C0603C102J5GACTU" 0603 1790,2810 r180 top
C7 "08055C105KAT2A" 0805_HV 1845,2625 r0 top
C8 "C1206C104M5RACTU" 1206 1960.2,1716.3 r180 top
C9 "08055C105KAT2A" 0805_HV 1845,2375 r180 top
C10 "08055C105KAT2A" 0805_HV 1790,2500 r90 top
C11 "GCE21BR71H104KA01L" FP-GCE21BR71H104KA01L_0805-MFG 1885,2500 r270 top
C12 "06035A220JAT2A" 0603 5730,2786 r90 top
C13 "06035A220JAT2A" 0603 5525,2786 r90 top
C14 "C0603C102J5GACTU" 0603 4920,2820 r180 top
C15 "06035A220JAT2A" 0603 5322,2786 r90 top
C16 "C1206C104M5RACTU" 1206 6320,2940 r90 top
C17 "08055C105KAT2A" 0805_HV 4967,2625 r0 top
C18 "C1206C104M5RACTU" 1206 6322,1768.07 r270 top
C19 "08055C105KAT2A" 0805_HV 4912,2500 r90 top
C20 "08055C105KAT2A" 0805_HV 4967,2375 r180 top
C21 "GCE21BR71H104KA01L" FP-GCE21BR71H104KA01L_0805-MFG 5007,2500 r270 top
C22 "C0603C102J5GACTU" 0603 5322,2214 r270 top
C23 "C0603C102J5GACTU" 0603 4930,2180 r180 top
C24 "06035A220JAT2A" 0603 5525,2214 r270 top
C25 "06035A220JAT2A" 0603 5730,2214 r270 top
C26 "06035A220JAT2A" 0603 5935,2214 r270 top
D1 "MMSZ5233BS-7-F" SOD-323 3100,4500 r0 top
D2 "MMSZ5233BS-7-F" SOD-323 3500,4350 r0 top
D3 "MMSZ5233BS-7-F" SOD-323 3918,4500 r0 top
D4 "SFH 2701" SFH_2701 2047.79,3248.03 r0 top
D5 "SFH 2701" SFH_2701 2048,3400 r180 top
D6 "SFH 2701" SFH_2701 5182,3248 r0 top
D7 "SFH 2701" SFH_2701 5182,3400 r180 top
D8 "SFH 2701" SFH_2701 5182,1725 r0 top
D9 "SFH 2701" SFH_2701 5182,1575 r180 top
FID1 "Fiducial" Fiducial10-20 552.76,4732.68 r0 top
FID2 "Fiducial" Fiducial10-20 582.28,267.32 r0 top
FID3 "Fiducial" Fiducial10-20 6337.01,257.48 r0 top
H1 "PMSSS 440 0025 PH" B_F_PMSSS4400025PH 287.01,4703.15 r0 top locked
H2 "PMSSS 440 0025 PH" B_F_PMSSS4400025PH 6701.18,4745.67 r0 top locked
H3 "PMSSS 440 0025 PH" B_F_PMSSS4400025PH 300,300 r0 top locked
H4 "PMSSS 440 0025 PH" B_F_PMSSS4400025PH 6661.81,300 r0 top locked
H5 "2203" Keystone_2203 287.01,4703.15 r180 bottom locked
H6 "2203" Keystone_2203 6801.18,4812.99 r180 bottom locked
H7 "2203" Keystone_2203 300,300 r180 bottom locked
H8 "2203" Keystone_2203 6761.81,200 r180 bottom locked
J1 "V+" Keystone_575-4 2750,4725 r0 top
J2 "Analog GND" Keystone_575-4 3500,4725 r0 top
J3 "V-" Keystone_575-4 4250,4725 r180 top
J4 "-INA" TE_5-1814832-1 1688,4150 r270 top
J5 "-INA Config" Samtec_TSM-103-01-X-SV 1787,3774 r0 top
J6 "+INA" TE_5-1814832-1 2783,4150 r270 top
J7 "+INA Config" Samtec_TSM-103-01-X-SV 2882,3774 r0 top
J8 "Output B" TE_5-1814832-1 1903.41,1432 r90 top
J9 "D_Bias" TE_5-1814832-1 2235.5,4150 r0 top
J10 "D_Bias" Samtec_TSM-103-01-X-SV 2334.5,3774 r0 top
J11 "V- Supply Select" Samtec_TSM-103-01-X-SV 4750,4702.9 r0 top
J12 "A1" Samtec_TSM-102-01-L-SV 600,1850 r90 top
J13 "A0" Samtec_TSM-102-01-L-SV 850,1850 r90 top
J14 "B1" Samtec_TSM-102-01-L-SV 1104.43,1850 r90 top
J15 "B0" Samtec_TSM-102-01-L-SV 1350,1850 r90 top
J16 "DGnd Select" Samtec_TSM-103-01-X-SV 375,3150 r90 top
J17 "-INA" TE_5-1814832-1 4805,4125 r270 top
J18 "-INA Config" Samtec_TSM-103-01-X-SV 4900,3750 r0 top
J19 "D_Bias" TE_5-1814832-1 5352.5,4125 r0 top
J20 "Output A" TE_5-1814832-1 6575,3000 r180 top
J21 "D_Bias" Samtec_TSM-103-01-X-SV 5452.93,3750 r0 top
J22 "+INA" TE_5-1814832-1 5900,4125 r270 top
J23 "+INA Config" Samtec_TSM-103-01-X-SV 6005.86,3750.28 r0 top
J24 "Output B" TE_5-1814832-1 6575,1712 r180 top
J25 "-INB" TE_5-1814832-1 5040,925 r90 top
J26 "-INB Config" Samtec_TSM-103-01-X-SV 4938.96,1300 r180 top
J27 "D_Bias" TE_5-1814832-1 5587.5,925 r0 top
J28 "D_Bias" Samtec_TSM-103-01-X-SV 5486.46,1300 r180 top
J29 "A1" Samtec_TSM-102-01-L-SV 3860,1850 r90 top
J30 "A0" Samtec_TSM-102-01-L-SV 4117.48,1850.2 r90 top
J31 "B1" Samtec_TSM-102-01-L-SV 4360,1850.2 r90 top
J32 "B0" Samtec_TSM-102-01-L-SV 4610,1850.2 r90 top
J33 "+INB" TE_5-1814832-1 6135,925 r90 top
J34 "+INB Config" Samtec_TSM-103-01-X-SV 6033.96,1300 r180 top
J35 "DGnd Select" Samtec_TSM-103-01-X-SV 3850,3148.23 r90 top
P1 "Digital Select Ext" FP-TSM-104-01-L-SV-P-TR_HDR4-MFG 255,2500 r90 top
P2 "Digital Select Ext" FP-TSM-104-01-L-SV-P-TR_HDR4-MFG 3750,2500 r90 top
R1 "ERJ-3GEY0R00V" FP-ERJ-3GEY0R00V_0603-MFG 2417,2676 r0 top
R2 "RG1608P-202-B-T5" 0603 2451,2786 r270 top
R3 "ERJ-3GEY0R00V" FP-ERJ-3GEY0R00V_0603-MFG 2624,2676 r0 top
R4 "RG1608P-204-B-T5" 0603 2660,2786 r270 top
R5 "RG1608P-102-B-T5" 0603 1940,2810 r0 top
R6 "RG1608P-102-B-T5" 0603 2211,2676 r0 top
R7 "RG1608P-102-B-T5" 0603 2245,2786 r270 top
R8 "CRCW08051K00FKEA" 0805_HV 1785.08,3307.09 r270 top
R9 "ERJ-3GEY0R00V" FP-ERJ-3GEY0R00V_0603-MFG 1980,2691 r90 top
R10 "RCG060310K0FKEA" 0603 2948,3536 r0 top
R11 "CRCW0805100RFKEA" 0805_HV 1903.41,2005 r270 top
R12 "CRCW120610K0FKEA" 1206 1958,1840.9 r180 top
R13 "ERJ-3GEY0R00V" FP-ERJ-3GEY0R00V_0603-MFG 1993.11,2325 r180 top
R14 "RCG060310K0FKEA" 0603 2798,3536 r0 top
R15 "RCG060310K0FKEA" 0603 2416.5,3536 r0 top
R16 "RT0603BRD0710KL" 0603 2055,2152 r180 top
R17 "RG1608P-102-B-T5" 0603 2055,2207 r180 top
R18 "RCG060310K0FKEA" 0603 2247.5,3536 r0 top
R19 "ERJ-3GEY0R00V" FP-ERJ-3GEY0R00V_0603-MFG 2247.07,2363.26 r0 top
R20 "ERJ-3GEY0R00V" FP-ERJ-3GEY0R00V_0603-MFG 2419,2363.26 r0 top
R21 "RG1608P-102-B-T5" 0603 2186.33,2254.1 r90 top
R22 "RG1608P-102-B-T5" 0603 2266.83,2254.1 r90 top
R23 "RG1608P-102-B-T5" 0603 2344,2254.1 r90 top
R24 "RCG060310K0FKEA" 0603 538.91,2085 r0 top
R25 "RCG060310K0FKEA" 0603 797.46,2085 r0 top
R26 "RCG060310K0FKEA" 0603 1056.01,2085 r0 top
R27 "RCG060310K0FKEA" 0603 1314.57,2085 r0 top
R28 "ERJ-3GEY0R00V" FP-ERJ-3GEY0R00V_0603-MFG 5762,2676 r0 top
R29 "CRCW08051K00FKEA" 0805_HV 4905,3305 r270 top
R30 "RG1608P-202-B-T5" 0603 5795,2786 r270 top
R31 "ERJ-3GEY0R00V" FP-ERJ-3GEY0R00V_0603-MFG 5558,2676 r0 top
R32 "RG1608P-102-B-T5" 0603 5060,2820 r0 top
R33 "RG1608P-203-B-T5" 0603 5590,2786 r270 top
R34 "ERJ-3GEY0R00V" FP-ERJ-3GEY0R00V_0603-MFG 5110,2691 r90 top
R35 "RCG060310K0FKEA" 0603 5520,3536 r0 top
R36 "CRCW0805100RFKEA" 0805_HV 6090,2940 r90 top
R37 "RG1608P-204-B-T5" 0603 5385,2786 r270 top
R38 "CRCW120610K0FKEA" 1206 6210,2940 r90 top
R39 "RCG060310K0FKEA" 0603 5375,3536 r0 top
R40 "RCG060310K0FKEA" 0603 6079,3536 r0 top
R41 "ERJ-3GEY0R00V" FP-ERJ-3GEY0R00V_0603-MFG 5110,2324.03 r270 top
R42 "CRCW0805100RFKEA" 0805_HV 6086,1768.07 r270 top
R43 "CRCW120610K0FKEA" 1206 6208.03,1768.07 r270 top
R44 "RCG060310K0FKEA" 0603 5929,3536 r0 top
R45 "CRCW08051K00FKEA" 0805_HV 4938.96,1657.2 r90 top
R46 "RCG060310K0FKEA" 0603 5406.5,1487.74 r180 top
R47 "RCG060310K0FKEA" 0603 5576.46,1487.74 r180 top
R48 "RG1608P-102-B-T5" 0603 5080,2180 r0 top
R49 "RG1608P-102-B-T5" 0603 5385,2214 r90 top
R50 "RCG060310K0FKEA" 0603 6115,1490 r0 top
R51 "ERJ-3GEY0R00V" FP-ERJ-3GEY0R00V_0603-MFG 5558,2324 r0 top
R52 "RG1608P-202-B-T5" 0603 5590,2214 r90 top
R53 "RCG060310K0FKEA" 0603 3800.9,2085 r0 top
R54 "RCG060310K0FKEA" 0603 4059.46,2085 r0 top
R55 "RCG060310K0FKEA" 0603 4318.01,2085 r0 top
R56 "RCG060310K0FKEA" 0603 4576.57,2085 r0 top
R57 "RCG060310K0FKEA" 0603 5965,1490 r0 top
R58 "ERJ-3GEY0R00V" FP-ERJ-3GEY0R00V_0603-MFG 5760,2324 r0 top
R59 "RG1608P-203-B-T5" 0603 5795,2214 r90 top
R60 "ERJ-3GEY0R00V" FP-ERJ-3GEY0R00V_0603-MFG 5967,2324 r0 top
R61 "RG1608P-204-B-T5" 0603 6000,2214 r90 top
TP1 "OUTSA/B2" Testpoint_Keystone_Compact#1 3050,2325 r0 top
TP2 "V+" Testpoint_Keystone_Compact#1 2112.2,4720 r0 top
TP3 "OUTSA/B1" Testpoint_Keystone_Compact#1 3050,2500 r0 top
TP4 "OUTA/B3" Testpoint_Keystone_Compact#1 3050,2675 r0 top
TP5 "IntDGnd/ExtDGnd" Testpoint_Keystone_Compact#1 750,3150 r0 top
TP6 "MUX Out" Testpoint_Keystone_Compact#1 2650,1950 r0 top
TP7 "+INB" Testpoint_Keystone_Compact#1 2650,2200 r0 top
TP8 "V-_Sel" Testpoint_Keystone_Compact#1 2615,1448 r0 top
TP9 "V-_Sel" Testpoint_Keystone_Compact#1 5300,4650 r180 top
TP10 "Analog GND" Testpoint_Keystone_Compact#1 6575,1000 r0 top
TP11 "Analog GND" Testpoint_Keystone_Compact#1 3050,3300 r0 top
TP12 "DGnd Ext" Testpoint_Keystone_Compact#1 327.76,3550 r0 top
TP13 "OUTSA2" Testpoint_Keystone_Compact#1 6100,3350 r0 top
TP14 "V-_Sel" Testpoint_Keystone_Compact#1 5987,381 r0 top
TP15 "V-_Sel" Testpoint_Keystone_Compact#1 3050,2150 r0 top
TP16 "OUTSA1" Testpoint_Keystone_Compact#1 5590,3350 r0 top
TP17 "Analog GND" Testpoint_Keystone_Compact#2 3050,1448 r0 top
TP18 "Analog GND" Testpoint_Keystone_Compact#1 6575,3550 r0 top
TP19 "OutA" Testpoint_Keystone_Compact#1 6575,2675 r0 top
TP20 "OutB" Testpoint_Keystone_Compact#1 6575,1387 r0 top
TP21 "IntDGnd/ExtDGnd" Testpoint_Keystone_Compact#1 4250,3148.23 r0 top
TP22 "OUTSB3" Testpoint_Keystone_Compact#1 6575,2150 r0 top
TP23 "OUTSB2" Testpoint_Keystone_Compact#1 6575,2325 r0 top
TP24 "DGnd Ext" Testpoint_Keystone_Compact#1 3825,3550 r0 top
TP25 "OUTSB1" Testpoint_Keystone_Compact#1 6575,2500 r0 top
U1 "OPA3S328RGR" RGR0020A 2047.24,2500 r0 top
U2 "OPA3S328RGR" RGR0020A 5170,2499.21 r0 top
ZZ1 "This Assembly Note is for PCB labels only" AssemblyNoteLabel 177.17,6131.89 r0 top
ZZ2 "These assemblies are ESD sensitive, ESD precautions shall be observed." AssemblyNote 167.32,6003.94 r0 top
ZZ3 "These assemblies must be clean and free from flux and all contaminants. Use of no clean flux is not acceptable." AssemblyNote 167.32,5866.14 r0 top
ZZ4 "These assemblies must comply with workmanship standards IPC-A-610 Class 2, unless otherwise specified." AssemblyNote 167.32,5728.35 r0 top

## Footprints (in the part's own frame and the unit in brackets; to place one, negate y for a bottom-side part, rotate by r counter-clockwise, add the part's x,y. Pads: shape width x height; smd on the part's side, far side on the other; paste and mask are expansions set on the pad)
0603 [mm] "0603 from SM-752 data"
  rect 1x0.95 smd: 1(-0.8,0) 2(0.8,0)
  silkscreen extent -1.52,-0.69 1.52,0.69
0805_HV [mil] "0805 with 30mil clearance between pads"
  rect 50x63 smd: 1(-40,0) 2(40,0)
  silkscreen extent -74,-40 74,40
1206 [mm] "1206 from SM-752 data"
  rect 1.3x1.85 smd: 1(-1.45,0) 2(1.45,0)
  silkscreen extent -2.4,-1.21 2.4,1.21
1206_190 [mm] "1206_190"
  rect 1.1x1.6 smd: 1(-1.7,0) 2(1.7,0)
  silkscreen extent -0.9,-1 0.9,1
AssemblyNote [mil] "Assembly Note"
AssemblyNoteLabel [mil] "Assembly Note for PCB Labels"
B_F_PMSSS4400025PH [mil] "MACHINE SCREW PAN PHILLIPS 4-40"
  round 230 hole 125: 1(0,0)
Fiducial10-20 [mm]
  round 1 smd mask+0: 1(0,0)
  Top Layer keep-out circle w1.178: c0,0 r0.5
FP-ERJ-3GEY0R00V_0603-MFG [mm]
  rrect15% 0.65x0.9 smd paste+0 mask+0: 1(-0.725,0) 2(0.725,0)
  silkscreen extent -1.03,-0.87 1.03,0.87
FP-GCE21BR71H104KA01L_0805-MFG [mm]
  rrect14% 0.7x1.3 smd paste+0 mask+0: 1(-1,0) 2(1,0)
  silkscreen extent -0.28,-0.72 0.28,0.72
FP-TSM-104-01-L-SV-P-TR_HDR4-MFG [mil]
  rrect8% 50x135 smd paste+0 mask+0: 1(150,-57.5) 2(50,57.5) 3(-50,-57.5) 4(-150,57.5)
  silkscreen extent -200,-93 202,53
Keystone_575-4 [mm] "Banana Jack"
  round 10 hole 5.45: 1(0,0)
Keystone_2203 [mil] "HEX STANDOFF 4-40 ALUMINUM 1/2\""
RGR0020A [mm] "QFN, 20-Leads, Body 3.5x3.5mm, Pitch 0.5mm, Thermal Pad 2.05x2.05mm, TI Recommended"
  rrect42% 0.6x0.24 smd: 1(-1.65,1) 2(-1.65,0.5) 3(-1.65,0) 4(-1.65,-0.5) 5(-1.65,-1) 11(1.65,-1) 12(1.65,-0.5) 13(1.65,0) 14(1.65,0.5) 15(1.65,1)
  rrect42% 0.24x0.6 smd: 6(-1,-1.65) 7(-0.5,-1.65) 8(0,-1.65) 9(0.5,-1.65) 10(1,-1.65) 16(1,1.65) 17(0.5,1.65) 18(0,1.65) 19(-0.5,1.65) 20(-1,1.65)
  rrect5% 2.05x2.05 smd paste-1.025: 21(0,0)
  silkscreen extent -1.97,-1.97 1.97,1.97
Samtec_TSM-102-01-L-SV [mm] "SAMTEC"
  rect 1.27x3.43 smd: 1(-1.27,1.46) 2(1.27,-1.46)
  silkscreen extent -0.2,1.7 0.2,2.1
Samtec_TSM-103-01-X-SV [mil] "Samtec recommended land pattern"
  rect 50x135 smd: 1(-100,57.5) 2(0,-57.5) 3(100,57.5)
  silkscreen extent -150,-50 150,50
SFH_2701 [mm] "SMD, 2-Leads, Body 3.2x1.5mm"
  rect 1.5x1.5 smd paste-0.05 mask+0: 1(-1.6,0) 2(1.6,0)
  silkscreen extent -2.6,-1 2.4,1
SOD-323 [mm] "NXP recommended land pattern"
  rect 0.6x0.6 smd paste-0.05: 1(-1.1,0) 2(1.1,0)
  silkscreen extent -2.06,-0.86 1.53,0.86
TE_5-1814832-1 [mm] "SMA Straight PCB Socket Die Cast, TH"
  round 2 hole 1.5: 1(0,0)
  round 2.1 hole 1.6: 2(-2.54,2.54) 3(-2.54,-2.54) 4(2.54,-2.54) 5(2.54,2.54)
  silkscreen extent -3.2,-3.2 3.2,3.2
Testpoint_Keystone_Compact#1 [mil] "Compact SMT test point"
  rect 185x135 smd: 1(0,0)
  silkscreen extent -110,-80 110,80
Testpoint_Keystone_Compact#2 [mil] "Compact SMT test point"
  rect 185x135 smd: 1(0,-16)
  silkscreen extent -110,-80 110,80

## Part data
C1 C4 C12 C13 C15 C24 C25 C26: library part CMP-0006775-4, "CAP, CERM, 22 pF, 50 V, +/- 5%, C0G/NP0, 0603"
C2 C3: library part CMP-0008692-1, "CAP, CERM, 10 uF, 25 V, +/- 20%, X7R, 1206_190"
C5 C6 C14 C22 C23: library part CMP-0006843-4, "CAP, CERM, 1000 pF, 50 V, +/- 5%, C0G/NP0, 0603"
C7 C9 C10 C17 C19 C20: library part CMP-0007634-2, "CAP, CERM, 1 uF, 50 V, +/- 10%, X7R, 0805"
C8 C16 C18: library part CMP-0008587-2, "CAP, CERM, 0.1 uF, 50 V, +/- 20%, X7R, 1206"
C11 C21: library part CMP-0088731-1, "0.1µF ±10% 50V Ceramic Capacitor X7R 0805 (2012 Metric)"
D1 D2 D3: library part CMP-0005856-3, "Diode, Zener, 6 V, 200 mW, SOD-323"
D4 D5 D6 D7 D8 D9: library part CMP-0002013-4, "High Speed PIN Photodiode, SMD"
FID1 FID2 FID3: library part CMP-0077181-1, "Fiducial mark.  There is nothing to buy or mount."
H1 H2 H3 H4: library part CMP-0003715-1, "MACHINE SCREW PAN PHILLIPS 4-40"
H5 H6 H7 H8: library part CMP-0003779-1
J1 J2 J3: library part CMP-0055165-1, "Standard Banana Jack, Uninsulated, 5.5mm"
J4 J6 J8 J9 J17 J19 J20 J22 J24 J25 J27 J33: library part CMP-0054990-1, "SMA Straight PCB Socket Die Cast, 50 Ohm, TH"
J5 J7 J10 J11 J16 J18 J21 J23 J26 J28 J34 J35: library part CMP-0075402-1, "Header, 100mil, 3x1, Gold, SMT"
J12 J13 J14 J15 J29 J30 J31 J32: library part CMP-0075467-1, "Header, 100mil, 2x1, Gold with Tin Tail, SMT"
P1 P2: library part CMP-0087359-1
R1 R3 R9 R13 R19 R20 R28 R31 R34 R41 R51 R58 R60: library part CMP-0089143-1, "0 Ohms Jumper 0.1W, 1/10W Chip Resistor 0603 (1608 Metric) Automotive AEC-Q200 Thick Film"
R2 R30 R52: library part CMP-0023463-3, "RES, 2.00 k, 0.1%, 0.1 W, 0603"
R4 R37 R61: library part CMP-0023465-3, "RES, 200 k, 0.1%, 0.1 W, 0603"
R5 R6 R7 R17 R21 R22 R23 R32 R48 R49: library part CMP-0023403-3, "RES, 1.00 k, 0.1%, 0.1 W, 0603"
R8 R29 R45: library part CMP-0020951-3, "RES, 1.00 k, 1%, 0.125 W, AEC-Q200 Grade 0, 0805"
R10 R14 R15 R18 R24 R25 R26 R27 R35 R39 R40 R44 R46 R47 R50 R53 R54 R55 R56 R57: library part CMP-0023337-3, "RES, 10.0 k, 1%, 0.1 W, 0603"
R11 R36 R42: library part CMP-0020835-3, "RES, 100, 1%, 0.125 W, AEC-Q200 Grade 0, 0805"
R12 R38 R43: library part CMP-0016577-1, "RES, 10.0 k, 1%, 0.25 W, 1206"
R16: library part CMP-0023653-3, "RES, 10.0 k, 0.1%, 0.1 W, 0603"
R33 R59: library part CMP-0023464-3, "RES, 20.0 k, 0.1%, 0.1 W, 0603"
TP1 TP2 TP3 TP4 TP5 TP6 TP7 TP8 TP9 TP10 TP11 TP12 TP13 TP14 TP15 TP16 TP17 TP18 TP19 TP20 TP21 TP22 TP23 TP24 TP25: library part CMP-0055153-1, "Test Point, Compact, SMT"
U1 U2: library part CMP-0860039-1, "40-MHz CMOS Operational Amplifier With Switches, RGR0020A (VQFN-20)"
ZZ1: library part CMP-0003616-3
ZZ2: library part CMP-0077236-1
ZZ3: library part CMP-0077237-1
ZZ4: library part CMP-0077238-1

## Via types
v1: diameter 34, hole 16, Top Layer to Bottom Layer, 61 vias
v2: diameter 35, hole 15, Top Layer to Bottom Layer, 28 vias
v3: diameter 30, hole 10, Top Layer to Bottom Layer, 22 vias
v4: diameter 24, hole 8, Top Layer to Bottom Layer, 16 vias
v5: diameter 50, hole 28, Top Layer to Bottom Layer, 9 vias

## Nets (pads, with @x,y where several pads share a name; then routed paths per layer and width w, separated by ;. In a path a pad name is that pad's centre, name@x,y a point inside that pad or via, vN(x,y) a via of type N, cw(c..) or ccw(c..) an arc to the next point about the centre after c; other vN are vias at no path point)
+IN_BIas: J7.2 R10.1 R14.2 R17.1 U1.17 | length 2390.5
  Top Layer w10: U1.17@2066.93,2564.96 2066.93,2629.51 2087.4,2649.98
  Top Layer w25: R17.1@2086.5,2207 v1(2086.5,2260.16) ; 2087.4,2649.98 v3(2087.4,2765) ; v3(2088.07,2950) 2088.07,2979.07 2287.32,3178.33 2603.83,3178.33 2882.32,3456.82 2882.32,3536 ; R14.2@2829.5,3536 2882.32,3536 ; J7.2@2882.32,3716.56 2882.32,3536 ; R10.1@2916.5,3536 2882.32,3536
  Int 3 V+ w25: v1(2086.5,2260.16) 2172.4,2346.06 2172.4,2680 v3(2087.4,2765)
  Bottom Layer w25: v3(2087.4,2765) 2088.07,2765.67 v3(2088.07,2950)
AmpB_FB: R13.1 R16.2 R17.2 U1.8 | length 293.1
  Top Layer w12: R13.1@2024.61,2325 2026.5,2326.89 2026.5,2356.5 2047.24,2377.24 U1.8@2047.24,2435.04
  Top Layer w25: R13.1@2024.61,2325 2024.61,2208.1 R17.2@2023.5,2207 2023.5,2156 2025.5,2154 R16.2@2026.5,2154.99
DGND_Sel_U1: J16.2 R24.1 R25.1 R26.1 R27.1 TP5.1 U1.3 | length 4272.1
  Top Layer w10: v4@1949.36,2512.36 1959.91,2501.81 1980.47,2501.81 U1.3@1982.28,2500
  Top Layer w25: v1(445,2085) R24.1@507.41,2085 ; v1(705,2085) R25.1@765.96,2085 ; v1(970,2085) R26.1@1024.52,2085 ; v1(1235,2084) 1236,2085 R27.1@1283.07,2085
  Top Layer w50: J16.2@432.5,3150 v2(750,3150)
  Int 3 V+ w25: v1(705,2085) 705,2486.79 750,2531.79 v2(750,3150)
  Bottom Layer w12: 1902,2494 1931,2494 v4@1943,2506
  Bottom Layer w25: v1(445,2085) 445,2015 463.91,1996.09 701.09,1996.09 ; v1@706.14,2083.86 706.14,2001.14 701.09,1996.09 ; v1(970,2085) 970,2000 966.09,1996.09 ; v1(1235,2084) 1235,1996.09 966.09,1996.09 ; 701.09,1996.09 966.09,1996.09
  Bottom Layer w50: v2(750,3150) 900,3150 1556.87,2493.13 1767.34,2493.13 1768.22,2494 1902,2494
  other v4: 1945,2506
DGND_SEL_U2: J35.2 R53.1 R54.1 R55.1 R56.1 TP21.1 U2.3 | length 4151.9
  Top Layer w10: v4(5068,2505) 5073.79,2499.21 U2.3@5105.04,2499.21
  Top Layer w25: v1(3705,2083) 3707,2085 R53.1@3769.41,2085 ; v1(3975,2085) R54.1@4027.96,2085 ; v1(4240,2085) R55.1@4286.51,2085 ; v1(4495,2084) 4496,2085 R56.1@4545.07,2085
  Top Layer w50: J35.2@3907.5,3148.23 v2(4250,3148.23)
  Int 3 V+ w25: v1(3975,2085) 4250,2360 v2(4250,3148.23)
  Bottom Layer w10: 5028.79,2499.21 5032.57,2503 v4@5072,2503
  Bottom Layer w25: v1(3705,2083) 3705,1995 3968.21,1995 ; v1(3975,2085) 3975,2001.79 3968.21,1995 ; v1(4240,2085) 4240,2005 4230,1995 ; v1(4495,2084) 4490,2079 4490,1995 4230,1995 ; 3968.21,1995 4230,1995
  Bottom Layer w50: v2(4250,3148.23) 4250,2919.21 4670,2499.21 5028.79,2499.21
GND: C2.1 C3.2 C6.2 C7.1 C8.1 C9.2 C14.2 C16.1 C17.1 C18.1 C20.2 C23.2 D1.2 D3.1 J2.1 J4.2 J4.3 J4.4 J4.5 J5.3 J6.2 J6.3 J6.4 J6.5 J7.3 J8.2 J8.3 J8.4 J8.5 J9.2 J9.3 J9.4 J9.5 J10.3 J11.3 J16.1 J17.2 J17.3 J17.4 J17.5 J18.3 J19.2 J19.3 J19.4 J19.5 J20.2 J20.3 J20.4 J20.5 J21.3 J22.2 J22.3 J22.4 J22.5 J23.3 J24.2 J24.3 J24.4 J24.5 J25.2 J25.3 J25.4 J25.5 J26.3 J27.2 J27.3 J27.4 J27.5 J28.3 J33.2 J33.3 J33.4 J33.5 J34.3 J35.1 R12.1 R16.1 R21.1 R38.1 R43.1 TP10.1 TP11.1 TP17.1 TP18.1 | length 3381.3
  Top Layer w25: v1(200,3050) J16.1@317.5,3050 ; v1(1700,2810) C6.2@1758.5,2810 ; v1(1735,2365) 1745,2375 C9.2@1805,2375 ; v1(1740,2645) 1785,2645 C7.1@1805,2625 ; R12.1@2015.09,1840.9 2089.1,1840.9 v1(2090,1840) ; C8.1@2017.29,1716.3 v1(2090,1716.3) ; R16.1@2086.5,2152 2086.5,2086.58 v1(2088.07,2085) ; v1(2184.36,2152) 2186.33,2153.97 R21.1@2186.33,2222.61 ; v1(3675,3045) 3678.23,3048.23 J35.1@3792.5,3048.23 ; v1(4800,2180) C23.2@4898.5,2180 ; v1(4830,2820) C14.2@4888.5,2820 ; v1(4840,2377) 4842,2375 C20.2@4927,2375 ; v1@4843.68,2625 4843.68,2623.68 4845,2625 C17.1@4927,2625 ; v1(6210,2800.96) R38.1@6210,2882.91 ; v1(6320,2801.46) C16.1@6320,2882.91
  Top Layer w50: J5.3@1887,3831.5 1954.5,3831.5 1955,3831 v1(1965,3831) ; J10.3@2434.5,3831.5 v1(2541.84,3831.5) v1@2542.5,3831.5 ; J7.3@2982,3831.5 v1(3137,3831.5) v1@3143.5,3831.5 ; D1.2@3143.31,4500 3166.93,4523.62 C2.1@3166.93,4720 3171.93,4725 J2.1@3500,4725 C3.2@3855.34,4725 3855.34,4519.36 D3.1@3874.69,4500 ; v1(4750,1242.5) J26.3@4838.96,1242.5 ; J11.3@4850,4760.4 4982.6,4760.4 v1(4983,4760) ; J18.3@5000,3807.5 v1(5090,3807.5) ; v1(5310,1240) 5312.5,1242.5 J28.3@5386.46,1242.5 ; J21.3@5552.93,3807.5 5649.72,3807.5 v1(5650,3807.78) ; v1@5860,1240 v1(5860,1242.5) J34.3@5933.96,1242.5 ; J23.3@6105.86,3807.78 6199.72,3807.78 v1(6200,3807.5)
  other v1: 4843.68,2633.68
  other v2: 4000,2498 475,2500.69 475,2596.58 3999.65,2600.23
  other v5: 6575,1000 3050,1432 3050,3300 6575,3550
MUXOUT: R19.1 TP6.1 U1.10 | length 861.8
  Top Layer w8: U1.10@2086.61,2435.04 2086.61,2371.64 2099.26,2359
  Top Layer w25: 2099.26,2359 2211.31,2359 v3(2215.57,2363.26)
  Bottom Layer w25: v3(2215.57,2363.26) 2329.59,2249.23 2447.33,2249.23 2650.66,2045.9 v1(2650.66,1950)
NetC1_1: C1.1 R1.1 | length 78.7
  Top Layer w25: R1.1@2385.5,2676 2386,2676.5 C1.1@2386,2754.5
NetC1_2: C1.2 C4.2 C5.2 D4.1 D5.2 R2.1 R4.1 R5.2 R7.1 R8.2 U1.18 | length 1752.5
  Top Layer w10: 2041.55,2631.47 2047.24,2625.78 U1.18@2047.24,2564.96
  Top Layer w25: R5.2@1971.5,2810 1975.5,2814 2041.55,2814 ; D4.1@1984.8,3248.03 2041.55,3191.28 2041.55,2814 ; 2041.55,2631.47 2041.55,2814 ; R4.1@2660,2817.5 C4.2@2590,2817.5 R2.1@2451,2817.5 C1.2@2386,2817.5 R7.1@2245,2817.5 C5.2@2180,2817.5 2176.5,2814 2041.55,2814
  Top Layer w50: R8.2@1785.08,3250 D4.1@1985.01,3250 ; D4.1@1984.8,3248.03 1985.01,3248.24 D4.1@1985.01,3250 ; D5.2@1985.01,3400 D4.1@1985.01,3250
NetC4_1: C4.1 R3.1 | length 79.5
  Top Layer w25: C4.1@2590,2754.5 2590,2678.5 R3.1@2592.5,2676
NetC5_1: C5.1 R6.1 | length 78.7
  Top Layer w25: R6.1@2179.5,2676 2180,2676.5 C5.1@2180,2754.5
